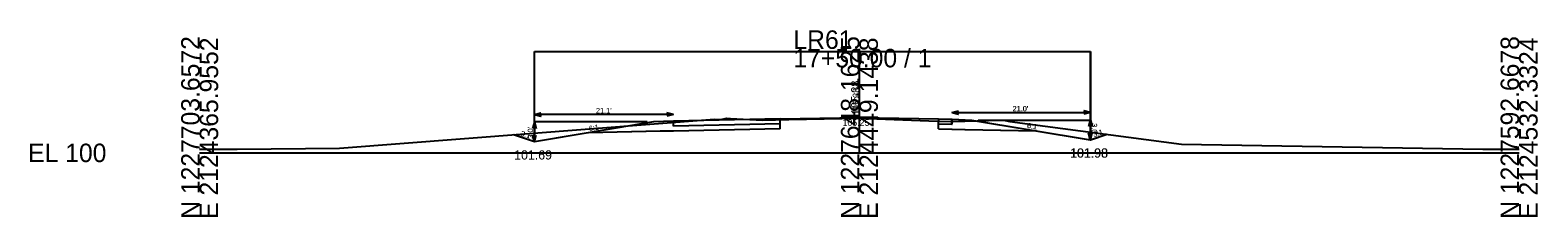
# Model space of a CAD drawing. Extents: x 2126751 to 2128979, y 1225108 to 1234639.
# Drawn here: x 2127750.9 to 2127979.4, y 1232607.5 to 1232635.8 of the extents above; entities that cross this region are included whole.
import ezdxf

# ---------------------------------------------------------------- set-up
doc = ezdxf.new("R2010")
doc.units = 0
for name, color, linetype in [('XS_CELL', 7, 'Continuous'), ('XS_M_DITCH', 7, 'Continuous'), ('XS_P_FINISHED_GRADE', 7, 'Continuous'), ('XS_P_FINISHED_GRADE_ELEV_TX', 7, 'Continuous'), ('XS_P_SUBGRADE_GRANULAR', 7, 'Continuous'), ('XS_P_SUBGRADE_LEVELING', 7, 'Continuous'), ('XS_P_SUBGRADE_PAVEMENT', 7, 'Continuous'), ('XS_P_TX_CLEARZONE', 7, 'Continuous'), ('XS_P_TX_DCH', 7, 'Continuous'), ('XS_P_TX_FS_BS', 7, 'Continuous'), ('XS_X_GROUND', 7, 'Continuous'), ('XS_X_GROUND_TX', 7, 'Continuous')]:
    doc.layers.add(name, color=color, linetype=linetype)

msp = doc.modelspace()

# ---------------------------------------------------------------- linework, layer by layer
at = {"layer": 'XS_CELL'}
for p, q in [((2127876.61, 1232617.21), (2127876.61, 1232632.97)), ((2127776.61, 1232617.21), (2127876.61, 1232617.21)), ((2127876.61, 1232617.21), (2127976.61, 1232617.21))]:
    msp.add_line(p, q, dxfattribs=at)
at = {"layer": 'XS_M_DITCH'}
for p, q in [((2127827.34, 1232618.9), (2127827.34, 1232632.59)), ((2127827.34, 1232632.59), (2127911.65, 1232632.59)), ((2127827.35, 1232618.9), (2127827.35, 1232632.59)), ((2127827.35, 1232632.59), (2127911.61, 1232632.59)), ((2127911.61, 1232632.59), (2127911.61, 1232619.19)), ((2127911.65, 1232632.59), (2127911.65, 1232619.19))]:
    msp.add_line(p, q, dxfattribs=at)
at = {"layer": 'XS_P_FINISHED_GRADE'}
for p, q in [((2127864.61, 1232622.35), (2127876.61, 1232622.59)), ((2127864.61, 1232622.35), (2127876.61, 1232622.59)), ((2127876.61, 1232622.59), (2127888.61, 1232622.35)), ((2127876.61, 1232622.59), (2127888.61, 1232622.35)), ((2127845.42, 1232621.9), (2127827.34, 1232618.9)), ((2127845.43, 1232621.9), (2127827.35, 1232618.9)), ((2127848.43, 1232622.02), (2127845.42, 1232621.9)), ((2127848.44, 1232622.02), (2127845.43, 1232621.9)), ((2127864.61, 1232622.35), (2127848.43, 1232622.02)), ((2127864.61, 1232622.35), (2127848.44, 1232622.02)), ((2127888.61, 1232622.35), (2127890.61, 1232622.31)), ((2127888.61, 1232622.35), (2127890.65, 1232622.31)), ((2127890.61, 1232622.31), (2127893.61, 1232622.19)), ((2127890.65, 1232622.31), (2127893.65, 1232622.19)), ((2127893.61, 1232622.19), (2127911.61, 1232619.19)), ((2127893.65, 1232622.19), (2127911.65, 1232619.19)), ((2127827.34, 1232618.9), (2127824.2, 1232619.94)), ((2127827.35, 1232618.9), (2127824.21, 1232619.94)), ((2127911.61, 1232619.19), (2127914.13, 1232620.03)), ((2127911.65, 1232619.19), (2127914.16, 1232620.02))]:
    msp.add_line(p, q, dxfattribs=at)
at = {"layer": 'XS_P_SUBGRADE_GRANULAR'}
for p, q in [((2127846.43, 1232620.48), (2127835.55, 1232620.26)), ((2127846.44, 1232620.48), (2127835.56, 1232620.26)), ((2127848.43, 1232620.52), (2127846.43, 1232620.48)), ((2127848.44, 1232620.52), (2127846.44, 1232620.48)), ((2127864.61, 1232620.85), (2127848.43, 1232620.52)), ((2127864.61, 1232620.85), (2127848.44, 1232620.52)), ((2127864.61, 1232620.85), (2127864.61, 1232621.6)), ((2127864.61, 1232620.85), (2127864.61, 1232621.6)), ((2127888.61, 1232620.85), (2127888.61, 1232621.6)), ((2127888.61, 1232620.85), (2127888.61, 1232621.6)), ((2127888.61, 1232620.85), (2127890.61, 1232620.81)), ((2127888.61, 1232620.85), (2127890.65, 1232620.81)), ((2127890.61, 1232620.81), (2127892.61, 1232620.77)), ((2127890.65, 1232620.81), (2127892.65, 1232620.77)), ((2127892.61, 1232620.77), (2127903.43, 1232620.55)), ((2127892.65, 1232620.77), (2127903.46, 1232620.55))]:
    msp.add_line(p, q, dxfattribs=at)
at = {"layer": 'XS_P_SUBGRADE_LEVELING'}
for p, q in [((2127864.61, 1232622.35), (2127864.61, 1232622.22)), ((2127864.61, 1232622.35), (2127864.61, 1232622.22)), ((2127864.61, 1232622.22), (2127865.89, 1232622.25)), ((2127864.61, 1232622.22), (2127865.89, 1232622.25)), ((2127865.89, 1232622.25), (2127876.63, 1232622.46)), ((2127865.89, 1232622.25), (2127876.63, 1232622.46)), ((2127876.63, 1232622.46), (2127888.46, 1232622.04)), ((2127876.63, 1232622.46), (2127888.46, 1232622.04)), ((2127888.46, 1232622.04), (2127888.61, 1232622.04)), ((2127888.46, 1232622.04), (2127888.61, 1232622.04)), ((2127888.61, 1232622.35), (2127888.61, 1232622.04)), ((2127888.61, 1232622.35), (2127888.61, 1232622.04))]:
    msp.add_line(p, q, dxfattribs=at)
at = {"layer": 'XS_P_SUBGRADE_PAVEMENT'}
for p, q in [((2127848.43, 1232621.27), (2127848.43, 1232622.02)), ((2127864.61, 1232621.6), (2127848.43, 1232621.27)), ((2127848.44, 1232621.27), (2127848.44, 1232622.02)), ((2127864.61, 1232621.6), (2127848.44, 1232621.27)), ((2127864.61, 1232621.6), (2127864.61, 1232622.22)), ((2127888.61, 1232621.6), (2127888.61, 1232622.04)), ((2127888.61, 1232621.6), (2127888.61, 1232622.04)), ((2127888.61, 1232621.6), (2127890.61, 1232621.56)), ((2127888.61, 1232621.6), (2127890.65, 1232621.56)), ((2127890.61, 1232621.56), (2127890.61, 1232622.31)), ((2127890.65, 1232621.56), (2127890.65, 1232622.31))]:
    msp.add_line(p, q, dxfattribs=at)
at = {"layer": 'XS_P_TX_CLEARZONE'}
for p, q in [((2127827.34, 1232623.02), (2127828.34, 1232623.27)), ((2127827.34, 1232623.02), (2127828.34, 1232622.77)), ((2127848.43, 1232623.02), (2127827.34, 1232623.02)), ((2127827.35, 1232623.02), (2127828.35, 1232623.27)), ((2127827.35, 1232623.02), (2127828.35, 1232622.77)), ((2127848.44, 1232623.02), (2127827.35, 1232623.02)), ((2127848.43, 1232623.02), (2127847.42, 1232623.27)), ((2127848.43, 1232623.02), (2127847.42, 1232622.77)), ((2127848.44, 1232623.02), (2127847.44, 1232623.27)), ((2127848.44, 1232623.02), (2127847.44, 1232622.77)), ((2127890.61, 1232623.31), (2127891.61, 1232623.56)), ((2127890.61, 1232623.31), (2127891.61, 1232623.06)), ((2127890.61, 1232623.31), (2127911.61, 1232623.31)), ((2127890.65, 1232623.31), (2127891.65, 1232623.56)), ((2127890.65, 1232623.31), (2127891.65, 1232623.06)), ((2127890.65, 1232623.31), (2127911.65, 1232623.31)), ((2127911.61, 1232623.31), (2127910.61, 1232623.56)), ((2127911.61, 1232623.31), (2127910.61, 1232623.06)), ((2127911.65, 1232623.31), (2127910.65, 1232623.56)), ((2127911.65, 1232623.31), (2127910.65, 1232623.06)), ((2127827.34, 1232621.9), (2127827.08, 1232620.9)), ((2127827.35, 1232621.9), (2127827.09, 1232620.9)), ((2127827.34, 1232621.9), (2127827.59, 1232620.9)), ((2127827.34, 1232621.9), (2127827.34, 1232618.9)), ((2127844.41, 1232621.9), (2127827.34, 1232621.9)), ((2127827.35, 1232621.9), (2127827.6, 1232620.9)), ((2127827.35, 1232621.9), (2127827.35, 1232618.9)), ((2127844.42, 1232621.9), (2127827.35, 1232621.9)), ((2127894.61, 1232622.19), (2127911.61, 1232622.19)), ((2127894.65, 1232622.19), (2127911.65, 1232622.19)), ((2127911.61, 1232622.19), (2127911.36, 1232621.19)), ((2127911.65, 1232622.19), (2127911.4, 1232621.19)), ((2127911.61, 1232622.19), (2127911.61, 1232619.19)), ((2127911.61, 1232622.19), (2127911.86, 1232621.19)), ((2127911.65, 1232622.19), (2127911.65, 1232619.19)), ((2127911.65, 1232622.19), (2127911.9, 1232621.19)), ((2127827.34, 1232618.9), (2127827.08, 1232619.9)), ((2127827.35, 1232618.9), (2127827.09, 1232619.9)), ((2127827.34, 1232618.9), (2127827.59, 1232619.9)), ((2127827.35, 1232618.9), (2127827.6, 1232619.9)), ((2127911.61, 1232619.19), (2127911.36, 1232620.19)), ((2127911.65, 1232619.19), (2127911.4, 1232620.19)), ((2127911.61, 1232619.19), (2127911.86, 1232620.19)), ((2127911.65, 1232619.19), (2127911.9, 1232620.19))]:
    msp.add_line(p, q, dxfattribs=at)
at = {"layer": 'XS_X_GROUND'}
for p, q in [((2127797.81, 1232617.9), (2127854.63, 1232622.31)), ((2127854.63, 1232622.31), (2127855.51, 1232622.29)), ((2127855.51, 1232622.29), (2127856.08, 1232622.35)), ((2127856.08, 1232622.35), (2127856.49, 1232622.45)), ((2127856.49, 1232622.45), (2127857.05, 1232622.42)), ((2127857.05, 1232622.42), (2127861.94, 1232622.17)), ((2127861.94, 1232622.17), (2127865.89, 1232622.25)), ((2127865.89, 1232622.25), (2127876.63, 1232622.46)), ((2127876.63, 1232622.46), (2127888.46, 1232622.04)), ((2127888.46, 1232622.04), (2127890.83, 1232621.96)), ((2127890.83, 1232621.96), (2127898.01, 1232622.18)), ((2127898.01, 1232622.18), (2127898.46, 1232622.19)), ((2127898.46, 1232622.19), (2127899.42, 1232621.97)), ((2127899.42, 1232621.97), (2127925.43, 1232618.54)), ((2127925.43, 1232618.54), (2127971.1, 1232617.77)), ((2127776.61, 1232617.76), (2127782.27, 1232617.75)), ((2127782.27, 1232617.75), (2127797.81, 1232617.9)), ((2127971.1, 1232617.77), (2127976.61, 1232617.76))]:
    msp.add_line(p, q, dxfattribs=at)

# ---------------------------------------------------------------- texts
at = {"layer": 'XS_CELL'}
for s, p in [('N 1227703.6572', (2127776.61, 1232607.21)), ('E 2124365.9552', (2127779.41, 1232607.21)), ('N 1227648.1625', (2127876.61, 1232607.21)), ('E 2124449.1438', (2127879.41, 1232607.21)), ('N 1227592.6678', (2127976.61, 1232607.21)), ('E 2124532.3324', (2127979.41, 1232607.21))]:
    msp.add_text(s, height=2.8, rotation=90, dxfattribs=at).set_placement(p)
for s, p in [('LR61', (2127866.61, 1232632.97)), ('17+50.00 / 1', (2127866.61, 1232630.17)), ('EL 100', (2127750.61, 1232615.81))]:
    msp.add_text(s, height=2.8, dxfattribs=at).set_placement(p)
at = {"layer": 'XS_P_FINISHED_GRADE_ELEV_TX'}
for height in [1.25, 1]:
    msp.add_text(' 105.38', height=height, rotation=90, dxfattribs=at).set_placement((2127876.61, 1232622.59))
at = {"layer": 'XS_P_TX_CLEARZONE'}
for s, p in [("21.1'", (2127836.68, 1232623.22)), ("21.1'", (2127836.69, 1232623.22)), ("21.0'", (2127899.82, 1232623.51)), ("21.0'", (2127899.86, 1232623.51))]:
    msp.add_text(s, height=0.8, dxfattribs=at).set_placement(p)
for rotation, p in [(90, (2127827.13, 1232619.38)), (90, (2127827.15, 1232619.38)), (270, (2127911.81, 1232621.71)), (270, (2127911.85, 1232621.71))]:
    msp.add_text("3.0'", height=0.8, rotation=rotation, dxfattribs=at).set_placement(p)
at = {"layer": 'XS_P_TX_DCH'}
for s, p in [('101.69', (2127824.28, 1232616.2)), ('101.69', (2127824.29, 1232616.2)), ('101.98', (2127908.54, 1232616.49)), ('101.98', (2127908.58, 1232616.49))]:
    msp.add_text(s, height=1.4, dxfattribs=at).set_placement(p)
at = {"layer": 'XS_P_TX_FS_BS'}
for s, rotation, p in [('3:1', 341.6421, (2127825.18, 1232619.83)), ('3:1', 341.6413, (2127825.19, 1232619.83)), ('6:1', 9.4207, (2127835.65, 1232620.49)), ('6:1', 9.4211, (2127835.66, 1232620.49)), ('6:1', 350.5377, (2127901.95, 1232621)), ('6:1', 350.5377, (2127901.99, 1232621)), ('3:1', 18.4349, (2127912.16, 1232619.58)), ('3:1', 18.4349, (2127912.19, 1232619.58))]:
    msp.add_text(s, height=0.8, rotation=rotation, dxfattribs=at).set_placement(p)
at = {"layer": 'XS_X_GROUND_TX'}
msp.add_text('105.25', height=1, dxfattribs=at).set_placement((2127874.05, 1232621.3))

doc.saveas('drawing.dxf')
